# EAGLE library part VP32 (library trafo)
TRANSFORMER 1 primary winding, 2 secondary windings BLOCK
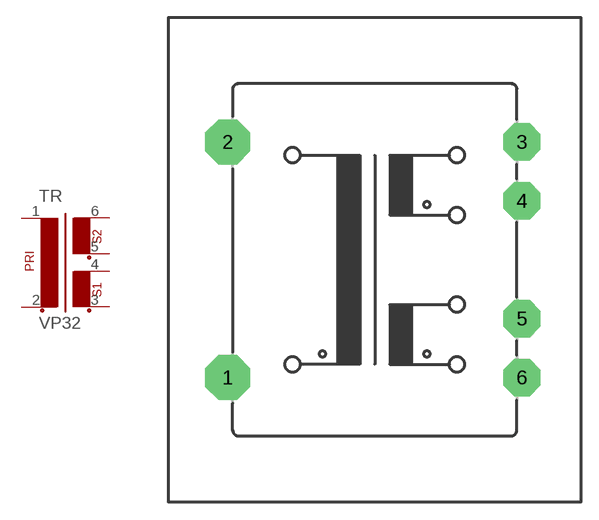
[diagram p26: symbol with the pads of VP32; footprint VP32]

Designator prefix TR

## VP32  [VP32]
1  1  pas
2  2  pas
3  3  pas
4  4  pas
5  5  pas
6  6  pas

## Footprint VP32 (pad centres in mm)
TRANSFORMER 1 primary winding, 2 secondary windings
drill 1.321 pad 3.81 octagon: 1 -12.497,-10.008; 2 -12.497,10.008
drill 1.321 pad 3.175 octagon: 3 12.497,10.008; 4 12.497,5.004; 5 12.497,-5.004; 6 12.497,-10.008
